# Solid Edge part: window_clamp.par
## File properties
Author: work
Template: Iso Part.par
Last saved by: Haley
Revision: 14
Application: Solid Edge
Material: Aluminum
Face Style: Steel
Fill Style: ANSI32(Steel)
Virtual Style: Machined steel
Coef. of Thermal Exp: 1.3e-05
Thermal Conductivity: 32.0
Specific Heat: 481.0
Modulus of Elasticity: 199947953000.0
Poisson's Ratio: 0.29
Yield Stress: 262000766.0
Ultimate Stress: 358527364.0
Elongation: 0.0
Density: 7833.000 kg/m^3
Accuracy: 0.990
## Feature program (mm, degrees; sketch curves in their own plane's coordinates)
sketch for "unnamed Protrusion 1" #1 plane through (0, 0, 0) normal (0, 0, 1) x-axis (1, 0, 0)
  circle centre (0, 0) radius 850
sketch for "unnamed Protrusion 1" #2 plane through (0, 0, 0) normal (0, 0, 1) x-axis (1, 0, 0)
  circle centre (0, 0) radius 926.2
extrude "unnamed Protrusion 1" add finite 50.8 along +normal
fillet "Round_1" radius 12.7
sketch for "Hole_1" plane through (0, 0, 0) normal (0, 0, -1) x-axis (1, 0, 0)
hole "Hole_1" diameter 19.05 through
sketch for "unnamed Hole 1" plane through (0, 0, 0) normal (0, 0, -1) x-axis (1, 0, 0)
  hole centre (-900.8, 0) bore radius 9.525
hole "unnamed Hole 1" through
sketch for "unnamed Hole 2" plane through (0, 0, 0) normal (0, 0, -1) x-axis (1, 0, 0)
  hole centre (900.8, 0) bore radius 9.525
hole "unnamed Hole 2" through
sketch for "unnamed Hole 3" plane through (0, 0, 0) normal (0, 0, -1) x-axis (1, 0, 0)
  hole centre (0, -900.8) bore radius 9.525
hole "unnamed Hole 3" through
pattern "unnamed Pattern 1" of "Hole_1", "unnamed Hole 1", "unnamed Hole 2", "unnamed Hole 3"
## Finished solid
Body 1: solid body, 9 faces, 13 edges, 0 vertices.
  Faces by surface: cylinder 6, plane 2, torus 1
  Edges by curve: circle 13
Bounding box of the edges (mm; curved faces can reach further): 1852.400 x 1852.400 x 50.800, from (-926.2, -926.2, 0) to (926.2, 926.2, 50.8).
Cylindrical faces by radius (mm): R9.525 x4, R850 x1, R926.2 x1
Toroidal faces (ring radius, tube radius in mm): R862.7 r12.7 x1
Planar faces by outward normal: +z 1, -z 1
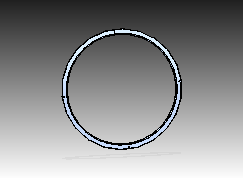
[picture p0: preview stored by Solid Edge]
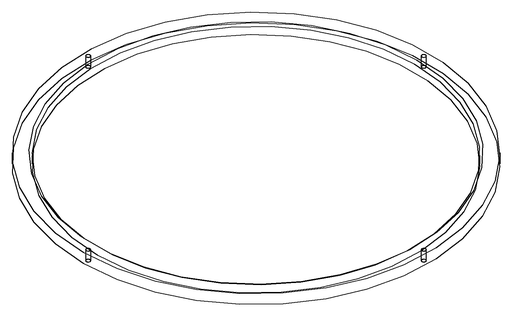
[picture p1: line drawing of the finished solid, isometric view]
